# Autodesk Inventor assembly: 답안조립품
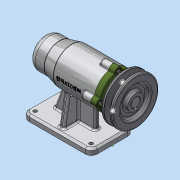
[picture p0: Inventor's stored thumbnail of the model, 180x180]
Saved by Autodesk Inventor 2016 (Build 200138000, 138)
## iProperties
Created: 2019-07
Part Number: 답안조립품
Material: 일반
Document SubType Name: Assembly
Designer: Administrator
Author: Administrator
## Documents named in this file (12)
- C:\Users\Administrator\Desktop\490704V1010\답안조립품.iam
- C:\Users\Administrator\Desktop\490704V1010\본체.ipt
- C:\Users\Administrator\Desktop\490704V1010\커버.ipt
- C:\Users\Administrator\Desktop\490704V1010\볼트 M4.ipt
- C:\Users\Administrator\Desktop\490704V1010\베어링 6004.ipt
- C:\Users\Administrator\Desktop\490704V1010\축.ipt
- C:\Users\Administrator\Desktop\490704V1010\어댑터슬리브.ipt
- C:\Users\Administrator\Desktop\490704V1010\베어링 51202.ipt
- C:\Users\Administrator\Desktop\490704V1010\오일 실.ipt
- C:\Users\Administrator\Desktop\490704V1010\V벨트풀리.ipt
- C:\Users\Administrator\Desktop\490704V1010\키 5 x 5 x 16.ipt
- C:\Users\Administrator\Desktop\490704V1010\멈춤나사 M3.ipt
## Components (1 placed, 1 different names)
1. V벨트풀리:1
